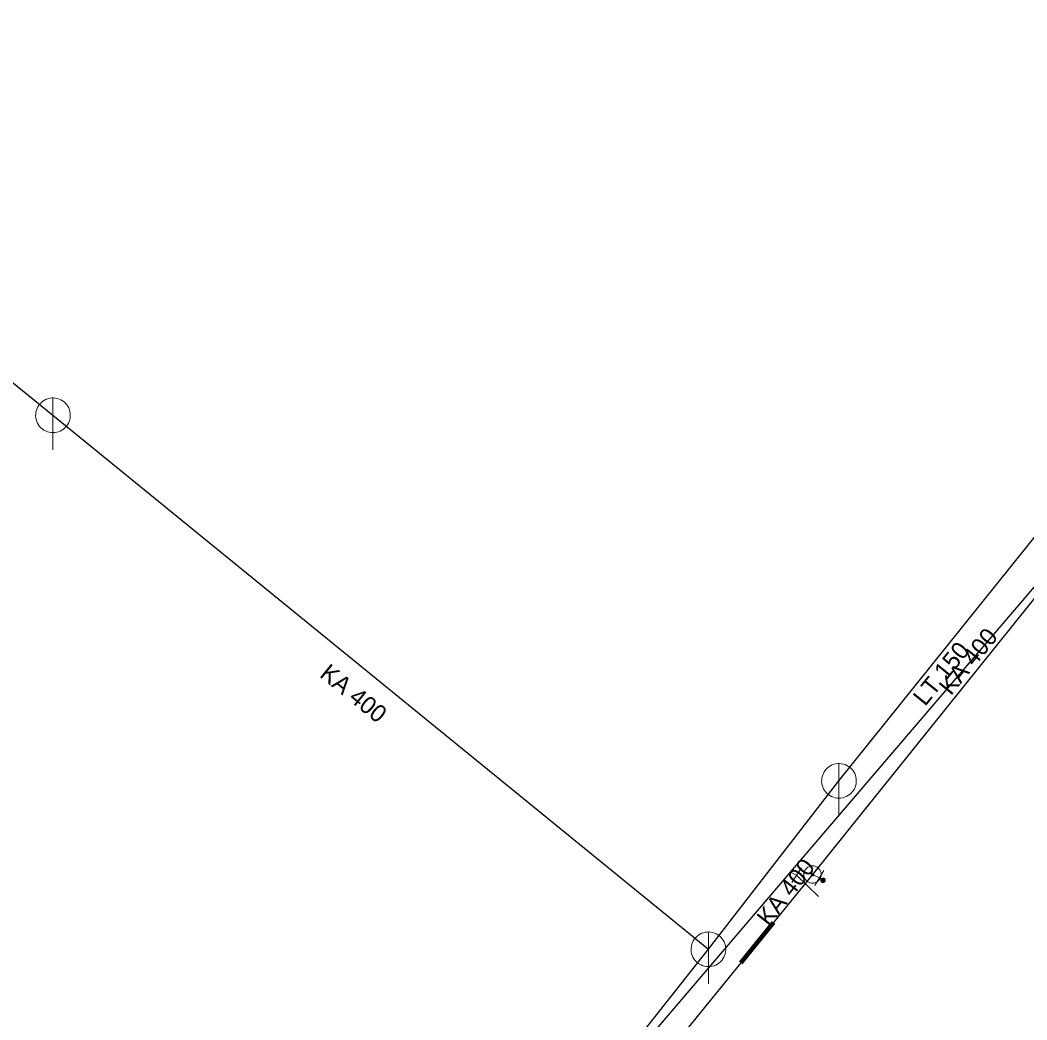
# Model space of a CAD drawing. Extents: x -790267 to -789874, y -989766 to -989454.
# Drawn here: x -790019.1 to -789961.1, y -989666 to -989608.4 of the extents above; entities that cross this region are included whole.
import ezdxf

# ---------------------------------------------------------------- set-up
doc = ezdxf.new("R2010")
doc.units = 0
doc.header["$LTSCALE"] = 0.4
doc.layers.add('1', color=7, linetype='Continuous')
for name, color, linetype, lineweight in [('13', 7, 'Continuous', 13), ('14', 7, 'Continuous', 13), ('17', 7, 'Continuous', 25), ('22', 7, 'Continuous', 13), ('3', 7, 'Continuous', 106), ('34', 7, 'Continuous', 13), ('47', 7, 'Continuous', 13), ('9', 7, 'Continuous', 13)]:
    doc.layers.add(name, color=color, linetype=linetype, lineweight=lineweight)

msp = doc.modelspace()

# ---------------------------------------------------------------- linework, layer by layer
at = {"layer": '13'}
msp.add_lwpolyline([(-789974.678, -989657.539), (-789974.331, -989657.706), (-789973.072, -989658.943)], dxfattribs=at)
at = {"layer": '14', "lineweight": 25}
for p, q in [((-790033.749, -989617.819), (-790017.22, -989631.198)), ((-790017.22, -989631.198), (-789979.42, -989661.98))]:
    msp.add_line(p, q, dxfattribs=at)
at = {"layer": '14'}
for p, q in [((-789973.42, -989657.67), (-789973.022, -989657.87)), ((-789973.022, -989657.87), (-789972.809, -989658))]:
    msp.add_line(p, q, dxfattribs=at)
at = {"layer": '14', "lineweight": 25}
for points in [[(-789971.89, -989652.27), (-789958.315, -989635.357), (-789937.51, -989610.1)], [(-790015.27, -989747.72), (-790017.28, -989707.56), (-789997.47, -989684.8), (-789979.42, -989661.98), (-789971.89, -989652.27)]]:
    msp.add_lwpolyline(points, dxfattribs=at)
at = {"layer": '17'}
for points in [[(-789931.949, -989608.42), (-789938.71, -989615.75), (-789947.76, -989626.449), (-789955.129, -989634.916), (-789973.42, -989657.67)], [(-789984.21, -989668.683), (-789974.678, -989657.539), (-789933.135, -989608.969)], [(-789973.42, -989657.67), (-789975.664, -989660.431), (-789977.556, -989662.759), (-789987.276, -989674.721), (-789997.491, -989687.245), (-790005.072, -989696.559), (-790016.278, -989710.509), (-790018.158, -989712.846), (-790025.949, -989722.546), (-790026.25, -989722.92), (-790028.329, -989725.546), (-790029.004, -989726.397), (-790029.656, -989727.219)]]:
    msp.add_lwpolyline(points, dxfattribs=at)
at = {"layer": '22'}
for p, q in [((-790017.22, -989633.198), (-790017.219, -989630.198)), ((-789971.89, -989654.27), (-789971.889, -989651.27)), ((-789979.42, -989663.98), (-789979.419, -989660.98))]:
    msp.add_line(p, q, dxfattribs=at)
for points in [[(-790016.22, -989631.198), (-790016.225, -989631.089), (-790016.243, -989630.981), (-790016.273, -989630.875), (-790016.313, -989630.774), (-790016.365, -989630.677), (-790016.427, -989630.587), (-790016.499, -989630.504), (-790016.579, -989630.43), (-790016.667, -989630.364), (-790016.761, -989630.309), (-790016.861, -989630.264), (-790016.966, -989630.231), (-790017.073, -989630.209), (-790017.182, -989630.199), (-790017.292, -989630.201), (-790017.4, -989630.215), (-790017.507, -989630.24), (-790017.61, -989630.277), (-790017.708, -989630.326), (-790017.8, -989630.384), (-790017.886, -989630.453), (-790017.963, -989630.53), (-790018.032, -989630.616), (-790018.091, -989630.708), (-790018.139, -989630.806), (-790018.176, -989630.909), (-790018.202, -989631.016), (-790018.216, -989631.124), (-790018.219, -989631.234), (-790018.209, -989631.343), (-790018.188, -989631.45), (-790018.154, -989631.554), (-790018.11, -989631.654), (-790018.055, -989631.749), (-790017.989, -989631.837), (-790017.915, -989631.917), (-790017.832, -989631.989), (-790017.742, -989632.051), (-790017.646, -989632.103), (-790017.544, -989632.144), (-790017.439, -989632.174), (-790017.331, -989632.192), (-790017.221, -989632.198), (-790017.112, -989632.192), (-790017.004, -989632.174), (-790016.899, -989632.145), (-790016.797, -989632.104), (-790016.7, -989632.052), (-790016.61, -989631.99), (-790016.527, -989631.919), (-790016.452, -989631.839), (-790016.387, -989631.751), (-790016.331, -989631.657), (-790016.287, -989631.557), (-790016.253, -989631.453), (-790016.231, -989631.345), (-790016.221, -989631.236)], [(-789970.89, -989652.27), (-789970.895, -989652.161), (-789970.913, -989652.053), (-789970.943, -989651.947), (-789970.983, -989651.846), (-789971.035, -989651.749), (-789971.097, -989651.659), (-789971.169, -989651.576), (-789971.249, -989651.502), (-789971.337, -989651.436), (-789971.431, -989651.381), (-789971.531, -989651.336), (-789971.636, -989651.303), (-789971.743, -989651.281), (-789971.852, -989651.271), (-789971.962, -989651.273), (-789972.07, -989651.287), (-789972.177, -989651.312), (-789972.28, -989651.349), (-789972.378, -989651.398), (-789972.47, -989651.456), (-789972.556, -989651.525), (-789972.633, -989651.602), (-789972.702, -989651.688), (-789972.761, -989651.78), (-789972.809, -989651.878), (-789972.846, -989651.981), (-789972.872, -989652.088), (-789972.886, -989652.196), (-789972.889, -989652.306), (-789972.879, -989652.415), (-789972.858, -989652.522), (-789972.824, -989652.626), (-789972.78, -989652.726), (-789972.725, -989652.821), (-789972.659, -989652.909), (-789972.585, -989652.989), (-789972.502, -989653.061), (-789972.412, -989653.123), (-789972.316, -989653.175), (-789972.214, -989653.216), (-789972.109, -989653.246), (-789972.001, -989653.264), (-789971.891, -989653.27), (-789971.782, -989653.264), (-789971.674, -989653.246), (-789971.569, -989653.217), (-789971.467, -989653.176), (-789971.37, -989653.124), (-789971.28, -989653.062), (-789971.197, -989652.991), (-789971.122, -989652.911), (-789971.057, -989652.823), (-789971.001, -989652.729), (-789970.957, -989652.629), (-789970.923, -989652.525), (-789970.901, -989652.417), (-789970.891, -989652.308)], [(-789978.42, -989661.98), (-789978.425, -989661.871), (-789978.443, -989661.763), (-789978.473, -989661.657), (-789978.513, -989661.556), (-789978.565, -989661.459), (-789978.627, -989661.369), (-789978.699, -989661.286), (-789978.779, -989661.212), (-789978.867, -989661.146), (-789978.961, -989661.091), (-789979.061, -989661.046), (-789979.166, -989661.013), (-789979.273, -989660.991), (-789979.382, -989660.981), (-789979.492, -989660.983), (-789979.6, -989660.997), (-789979.707, -989661.022), (-789979.81, -989661.059), (-789979.908, -989661.108), (-789980, -989661.166), (-789980.086, -989661.235), (-789980.163, -989661.312), (-789980.232, -989661.398), (-789980.291, -989661.49), (-789980.339, -989661.588), (-789980.376, -989661.691), (-789980.402, -989661.798), (-789980.416, -989661.906), (-789980.419, -989662.016), (-789980.409, -989662.125), (-789980.388, -989662.232), (-789980.354, -989662.336), (-789980.31, -989662.436), (-789980.255, -989662.531), (-789980.189, -989662.619), (-789980.115, -989662.699), (-789980.032, -989662.771), (-789979.942, -989662.833), (-789979.846, -989662.885), (-789979.744, -989662.926), (-789979.639, -989662.956), (-789979.531, -989662.974), (-789979.421, -989662.98), (-789979.312, -989662.974), (-789979.204, -989662.956), (-789979.099, -989662.927), (-789978.997, -989662.886), (-789978.9, -989662.834), (-789978.81, -989662.772), (-789978.727, -989662.701), (-789978.652, -989662.621), (-789978.587, -989662.533), (-789978.531, -989662.439), (-789978.487, -989662.339), (-789978.453, -989662.235), (-789978.431, -989662.127), (-789978.421, -989662.018)]]:
    msp.add_lwpolyline(points, close=True, dxfattribs=at)
at = {"layer": '3'}
msp.add_line((-789975.664, -989660.431), (-789977.556, -989662.759), dxfattribs=at)
at = {"layer": '3', "lineweight": 100}
msp.add_line((-789975.664, -989660.431), (-789977.556, -989662.759), dxfattribs=at)
at = {"layer": '34'}
for p, q in [((-789974.053, -989657.29), (-789974.609, -989658.121)), ((-789972.761, -989657.442), (-789973.282, -989658.296))]:
    msp.add_line(p, q, dxfattribs=at)
at = {"layer": '47'}
for points in [[(-789973.735, -989658.058), (-789973.693, -989658.088), (-789973.647, -989658.115), (-789973.6, -989658.135), (-789973.55, -989658.152), (-789973.499, -989658.163), (-789973.446, -989658.168), (-789973.394, -989658.168), (-789973.342, -989658.163), (-789973.291, -989658.152), (-789973.241, -989658.137), (-789973.193, -989658.115), (-789973.148, -989658.089), (-789973.106, -989658.059), (-789973.067, -989658.023), (-789973.031, -989657.985), (-789973.001, -989657.943), (-789972.974, -989657.897), (-789972.953, -989657.849), (-789972.937, -989657.8), (-789972.926, -989657.749), (-789972.921, -989657.696), (-789972.92, -989657.644), (-789972.926, -989657.591), (-789972.936, -989657.541), (-789972.952, -989657.491), (-789972.974, -989657.443), (-789973, -989657.397), (-789973.03, -989657.356), (-789973.066, -989657.317), (-789973.104, -989657.281), (-789973.146, -989657.251), (-789973.192, -989657.224), (-789973.24, -989657.202), (-789973.289, -989657.187), (-789973.34, -989657.176), (-789973.392, -989657.17), (-789973.445, -989657.17), (-789973.497, -989657.175), (-789973.548, -989657.186), (-789973.598, -989657.202), (-789973.646, -989657.224), (-789973.691, -989657.249), (-789973.733, -989657.28), (-789973.772, -989657.316), (-789973.808, -989657.354), (-789973.838, -989657.396), (-789973.865, -989657.442), (-789973.886, -989657.489), (-789973.902, -989657.539), (-789973.913, -989657.59), (-789973.919, -989657.642), (-789973.919, -989657.694), (-789973.913, -989657.746), (-789973.902, -989657.798), (-789973.887, -989657.848), (-789973.865, -989657.896), (-789973.839, -989657.94), (-789973.809, -989657.983), (-789973.773, -989658.022)], [(-789973.471, -989657.733), (-789973.464, -989657.739), (-789973.457, -989657.742), (-789973.449, -989657.746), (-789973.441, -989657.749), (-789973.432, -989657.75), (-789973.424, -989657.751), (-789973.415, -989657.752), (-789973.407, -989657.751), (-789973.399, -989657.748), (-789973.39, -989657.746), (-789973.382, -989657.742), (-789973.375, -989657.738), (-789973.368, -989657.733), (-789973.362, -989657.728), (-789973.356, -989657.721), (-789973.35, -989657.714), (-789973.347, -989657.707), (-789973.343, -989657.699), (-789973.34, -989657.691), (-789973.339, -989657.682), (-789973.338, -989657.674), (-789973.337, -989657.665), (-789973.338, -989657.657), (-789973.34, -989657.648), (-789973.343, -989657.64), (-789973.347, -989657.632), (-789973.351, -989657.625), (-789973.356, -989657.618), (-789973.361, -989657.612), (-789973.368, -989657.606), (-789973.375, -989657.6), (-789973.382, -989657.597), (-789973.39, -989657.593), (-789973.398, -989657.59), (-789973.407, -989657.589), (-789973.414, -989657.587), (-789973.424, -989657.587), (-789973.432, -989657.588), (-789973.441, -989657.59), (-789973.449, -989657.593), (-789973.457, -989657.597), (-789973.464, -989657.601), (-789973.471, -989657.606), (-789973.477, -989657.611), (-789973.483, -989657.618), (-789973.489, -989657.625), (-789973.492, -989657.632), (-789973.496, -989657.64), (-789973.499, -989657.648), (-789973.5, -989657.657), (-789973.502, -989657.664), (-789973.502, -989657.674), (-789973.501, -989657.682), (-789973.498, -989657.69), (-789973.496, -989657.699), (-789973.492, -989657.707), (-789973.488, -989657.714), (-789973.483, -989657.721), (-789973.478, -989657.727)]]:
    msp.add_lwpolyline(points, close=True, dxfattribs=at)
at = {"layer": '9'}
for points in [[(-789972.935, -989658), (-789972.935, -989658.013), (-789972.933, -989658.026), (-789972.93, -989658.039), (-789972.925, -989658.051), (-789972.919, -989658.063), (-789972.912, -989658.074), (-789972.904, -989658.084), (-789972.894, -989658.094), (-789972.884, -989658.102), (-789972.873, -989658.109), (-789972.861, -989658.115), (-789972.849, -989658.12), (-789972.836, -989658.123), (-789972.823, -989658.125), (-789972.81, -989658.127), (-789972.797, -989658.126), (-789972.784, -989658.124), (-789972.771, -989658.121), (-789972.759, -989658.116), (-789972.747, -989658.11), (-789972.736, -989658.103), (-789972.726, -989658.095), (-789972.716, -989658.085), (-789972.708, -989658.075), (-789972.701, -989658.064), (-789972.695, -989658.052), (-789972.69, -989658.04), (-789972.687, -989658.027), (-789972.685, -989658.014), (-789972.683, -989658.001), (-789972.684, -989657.988), (-789972.686, -989657.975), (-789972.689, -989657.962), (-789972.694, -989657.95), (-789972.7, -989657.938), (-789972.707, -989657.927), (-789972.715, -989657.917), (-789972.725, -989657.907), (-789972.735, -989657.899), (-789972.746, -989657.892), (-789972.758, -989657.886), (-789972.77, -989657.881), (-789972.783, -989657.878), (-789972.796, -989657.876), (-789972.809, -989657.875), (-789972.822, -989657.875), (-789972.835, -989657.877), (-789972.848, -989657.88), (-789972.86, -989657.885), (-789972.872, -989657.891), (-789972.883, -989657.898), (-789972.893, -989657.906), (-789972.903, -989657.916), (-789972.911, -989657.926), (-789972.918, -989657.937), (-789972.924, -989657.949), (-789972.929, -989657.961), (-789972.932, -989657.974), (-789972.934, -989657.987)], [(-789972.915, -989658), (-789972.916, -989658.011), (-789972.914, -989658.022), (-789972.911, -989658.033), (-789972.907, -989658.043), (-789972.902, -989658.053), (-789972.896, -989658.062), (-789972.889, -989658.071), (-789972.881, -989658.079), (-789972.872, -989658.086), (-789972.863, -989658.092), (-789972.853, -989658.097), (-789972.843, -989658.101), (-789972.832, -989658.104), (-789972.821, -989658.107), (-789972.81, -989658.107), (-789972.799, -989658.107), (-789972.788, -989658.105), (-789972.777, -989658.102), (-789972.767, -989658.098), (-789972.757, -989658.093), (-789972.748, -989658.087), (-789972.739, -989658.08), (-789972.731, -989658.072), (-789972.724, -989658.063), (-789972.718, -989658.054), (-789972.713, -989658.044), (-789972.709, -989658.034), (-789972.706, -989658.023), (-789972.704, -989658.012), (-789972.703, -989658.001), (-789972.703, -989657.99), (-789972.705, -989657.979), (-789972.708, -989657.968), (-789972.712, -989657.958), (-789972.717, -989657.948), (-789972.723, -989657.939), (-789972.73, -989657.93), (-789972.738, -989657.922), (-789972.747, -989657.915), (-789972.756, -989657.909), (-789972.766, -989657.904), (-789972.776, -989657.9), (-789972.787, -989657.897), (-789972.798, -989657.895), (-789972.809, -989657.895), (-789972.82, -989657.894), (-789972.831, -989657.896), (-789972.842, -989657.899), (-789972.852, -989657.903), (-789972.862, -989657.908), (-789972.871, -989657.914), (-789972.88, -989657.921), (-789972.888, -989657.929), (-789972.895, -989657.938), (-789972.901, -989657.947), (-789972.906, -989657.957), (-789972.91, -989657.967), (-789972.913, -989657.978), (-789972.915, -989657.989)], [(-789972.896, -989658), (-789972.896, -989658.009), (-789972.895, -989658.018), (-789972.892, -989658.027), (-789972.889, -989658.035), (-789972.885, -989658.043), (-789972.88, -989658.051), (-789972.874, -989658.058), (-789972.868, -989658.064), (-789972.861, -989658.07), (-789972.853, -989658.075), (-789972.845, -989658.079), (-789972.837, -989658.082), (-789972.828, -989658.085), (-789972.819, -989658.086), (-789972.81, -989658.088), (-789972.801, -989658.087), (-789972.792, -989658.086), (-789972.783, -989658.083), (-789972.775, -989658.08), (-789972.767, -989658.076), (-789972.759, -989658.071), (-789972.752, -989658.065), (-789972.746, -989658.059), (-789972.74, -989658.052), (-789972.735, -989658.044), (-789972.731, -989658.036), (-789972.728, -989658.028), (-789972.725, -989658.019), (-789972.724, -989658.01), (-789972.722, -989658.001), (-789972.723, -989657.992), (-789972.724, -989657.983), (-789972.727, -989657.974), (-789972.73, -989657.966), (-789972.734, -989657.958), (-789972.739, -989657.95), (-789972.745, -989657.943), (-789972.751, -989657.937), (-789972.758, -989657.931), (-789972.766, -989657.926), (-789972.774, -989657.922), (-789972.782, -989657.919), (-789972.791, -989657.916), (-789972.8, -989657.915), (-789972.809, -989657.914), (-789972.818, -989657.914), (-789972.827, -989657.915), (-789972.836, -989657.918), (-789972.844, -989657.921), (-789972.852, -989657.925), (-789972.86, -989657.93), (-789972.867, -989657.936), (-789972.873, -989657.942), (-789972.879, -989657.949), (-789972.884, -989657.957), (-789972.888, -989657.965), (-789972.891, -989657.973), (-789972.894, -989657.982), (-789972.895, -989657.991)], [(-789972.876, -989658), (-789972.876, -989658.007), (-789972.875, -989658.014), (-789972.874, -989658.021), (-789972.871, -989658.027), (-789972.868, -989658.033), (-789972.864, -989658.039), (-789972.86, -989658.045), (-789972.855, -989658.05), (-789972.849, -989658.054), (-789972.843, -989658.058), (-789972.837, -989658.061), (-789972.831, -989658.064), (-789972.824, -989658.065), (-789972.817, -989658.068), (-789972.81, -989658.068), (-789972.803, -989658.068), (-789972.796, -989658.066), (-789972.789, -989658.065), (-789972.783, -989658.062), (-789972.776, -989658.059), (-789972.771, -989658.055), (-789972.765, -989658.051), (-789972.76, -989658.046), (-789972.756, -989658.04), (-789972.752, -989658.034), (-789972.749, -989658.028), (-789972.746, -989658.022), (-789972.744, -989658.015), (-789972.743, -989658.008), (-789972.742, -989658.001), (-789972.742, -989657.994), (-789972.743, -989657.987), (-789972.745, -989657.98), (-789972.748, -989657.974), (-789972.751, -989657.967), (-789972.755, -989657.962), (-789972.759, -989657.956), (-789972.764, -989657.951), (-789972.77, -989657.947), (-789972.775, -989657.943), (-789972.782, -989657.94), (-789972.788, -989657.937), (-789972.795, -989657.935), (-789972.802, -989657.934), (-789972.809, -989657.934), (-789972.816, -989657.934), (-789972.823, -989657.934), (-789972.83, -989657.936), (-789972.836, -989657.939), (-789972.842, -989657.942), (-789972.848, -989657.946), (-789972.854, -989657.95), (-789972.859, -989657.955), (-789972.863, -989657.961), (-789972.867, -989657.966), (-789972.87, -989657.973), (-789972.873, -989657.979), (-789972.874, -989657.986), (-789972.876, -989657.993)], [(-789972.856, -989658), (-789972.856, -989658.005), (-789972.856, -989658.01), (-789972.855, -989658.015), (-789972.853, -989658.019), (-789972.851, -989658.024), (-789972.848, -989658.028), (-789972.845, -989658.031), (-789972.841, -989658.035), (-789972.838, -989658.038), (-789972.834, -989658.041), (-789972.829, -989658.043), (-789972.825, -989658.045), (-789972.82, -989658.046), (-789972.815, -989658.048), (-789972.81, -989658.048), (-789972.805, -989658.048), (-789972.8, -989658.047), (-789972.795, -989658.046), (-789972.791, -989658.044), (-789972.786, -989658.042), (-789972.782, -989658.039), (-789972.778, -989658.036), (-789972.775, -989658.032), (-789972.772, -989658.029), (-789972.769, -989658.025), (-789972.767, -989658.02), (-789972.765, -989658.016), (-789972.764, -989658.011), (-789972.763, -989658.006), (-789972.762, -989658.001), (-789972.762, -989657.996), (-789972.763, -989657.991), (-789972.764, -989657.986), (-789972.766, -989657.982), (-789972.768, -989657.977), (-789972.771, -989657.973), (-789972.774, -989657.969), (-789972.777, -989657.966), (-789972.781, -989657.963), (-789972.785, -989657.96), (-789972.79, -989657.958), (-789972.794, -989657.956), (-789972.799, -989657.955), (-789972.804, -989657.954), (-789972.809, -989657.954), (-789972.814, -989657.954), (-789972.819, -989657.955), (-789972.824, -989657.955), (-789972.828, -989657.957), (-789972.833, -989657.959), (-789972.837, -989657.962), (-789972.84, -989657.965), (-789972.844, -989657.968), (-789972.847, -989657.972), (-789972.85, -989657.976), (-789972.852, -989657.981), (-789972.854, -989657.985), (-789972.855, -989657.99), (-789972.856, -989657.995)], [(-789972.836, -989658), (-789972.836, -989658.003), (-789972.837, -989658.006), (-789972.836, -989658.008), (-789972.835, -989658.011), (-789972.834, -989658.014), (-789972.832, -989658.016), (-789972.83, -989658.018), (-789972.828, -989658.02), (-789972.826, -989658.022), (-789972.824, -989658.024), (-789972.821, -989658.026), (-789972.818, -989658.027), (-789972.816, -989658.027), (-789972.813, -989658.028), (-789972.81, -989658.028), (-789972.807, -989658.028), (-789972.804, -989658.028), (-789972.801, -989658.027), (-789972.799, -989658.026), (-789972.796, -989658.025), (-789972.794, -989658.023), (-789972.791, -989658.021), (-789972.789, -989658.019), (-789972.788, -989658.017), (-789972.786, -989658.015), (-789972.785, -989658.012), (-789972.783, -989658.009), (-789972.783, -989658.007), (-789972.782, -989658.004), (-789972.781, -989658.001), (-789972.782, -989657.998), (-789972.782, -989657.995), (-789972.783, -989657.992), (-789972.784, -989657.99), (-789972.785, -989657.987), (-789972.787, -989657.985), (-789972.788, -989657.982), (-789972.79, -989657.98), (-789972.793, -989657.979), (-789972.795, -989657.977), (-789972.798, -989657.976), (-789972.8, -989657.975), (-789972.803, -989657.974), (-789972.806, -989657.974), (-789972.809, -989657.973), (-789972.812, -989657.974), (-789972.815, -989657.973), (-789972.817, -989657.975), (-789972.82, -989657.975), (-789972.823, -989657.976), (-789972.825, -989657.978), (-789972.827, -989657.979), (-789972.829, -989657.981), (-789972.831, -989657.984), (-789972.833, -989657.986), (-789972.834, -989657.989), (-789972.835, -989657.991), (-789972.836, -989657.994), (-789972.836, -989657.997)], [(-789972.817, -989658), (-789972.817, -989658.002), (-789972.817, -989658.002), (-789972.816, -989658.002), (-789972.816, -989658.004), (-789972.817, -989658.005), (-789972.815, -989658.005), (-789972.815, -989658.005), (-789972.815, -989658.007), (-789972.815, -989658.007), (-789972.814, -989658.008), (-789972.812, -989658.008), (-789972.812, -989658.008), (-789972.812, -989658.009), (-789972.81, -989658.009), (-789972.81, -989658.009), (-789972.809, -989658.009), (-789972.808, -989658.009), (-789972.808, -989658.008), (-789972.807, -989658.008), (-789972.805, -989658.008), (-789972.805, -989658.007), (-789972.805, -989658.007), (-789972.804, -989658.006), (-789972.804, -989658.006), (-789972.802, -989658.005), (-789972.802, -989658.004), (-789972.801, -989658.003), (-789972.801, -989658.003), (-789972.801, -989658.002), (-789972.801, -989658.001), (-789972.801, -989658), (-789972.801, -989657.999), (-789972.801, -989657.999), (-789972.802, -989657.998), (-789972.802, -989657.997), (-789972.803, -989657.996), (-789972.803, -989657.996), (-789972.804, -989657.995), (-789972.804, -989657.995), (-789972.805, -989657.994), (-789972.806, -989657.994), (-789972.807, -989657.993), (-789972.807, -989657.993), (-789972.808, -989657.993), (-789972.809, -989657.993), (-789972.81, -989657.993), (-789972.811, -989657.993), (-789972.811, -989657.993), (-789972.812, -989657.994), (-789972.813, -989657.993), (-789972.814, -989657.995), (-789972.814, -989657.995), (-789972.815, -989657.995), (-789972.815, -989657.995), (-789972.816, -989657.997), (-789972.816, -989657.998), (-789972.816, -989657.999), (-789972.817, -989657.999), (-789972.817, -989658)]]:
    msp.add_lwpolyline(points, close=True, dxfattribs=at)

# ---------------------------------------------------------------- texts
at = {"layer": '1'}
for s, rotation, p in [('KA 400', 51, (-789965.431, -989647.395)), ('LT 150', 51, (-789966.921, -989648.013)), ('KA 400', 321, (-790001.898, -989646.233)), ('KA 400', 52, (-789975.924, -989660.712))]:
    msp.add_text(s, height=1, rotation=rotation, dxfattribs=at).set_placement(p)

doc.saveas('drawing.dxf')
